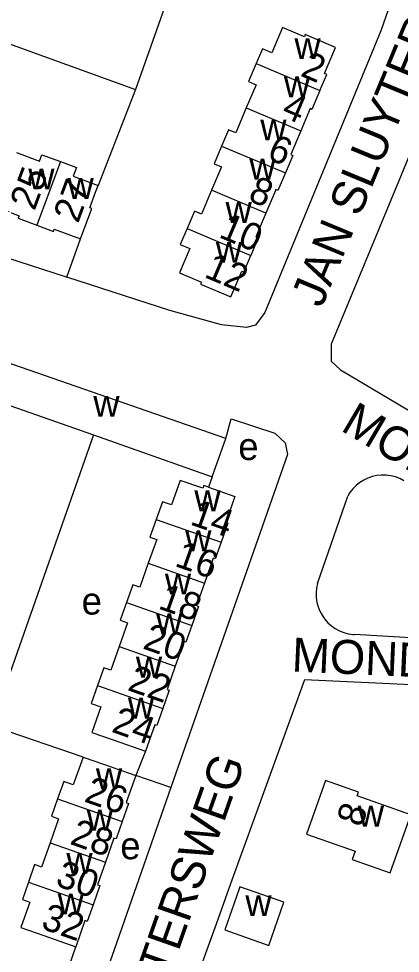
# Model space of a CAD drawing. Extents: x 162804 to 165059, y 381530 to 382901.
# Drawn here: x 163868.3 to 163924.4, y 381888 to 382025.5 of the extents above; entities that cross this region are included whole.
import ezdxf

# ---------------------------------------------------------------- set-up
doc = ezdxf.new("R2010")
doc.units = 0
for name, color, linetype in [('BLT_Basislijn', 7, 'Continuous'), ('BLT_Bebouwing', 7, 'Continuous'), ('BLT_Centroide', 7, 'Continuous'), ('BLT_Huisnummer', 7, 'Continuous'), ('BLT_Huisnummer_ tussenligend', 7, 'Continuous'), ('BLT_Onderverdeling_panden', 7, 'Continuous'), ('BLT_Straatnaam', 7, 'Continuous')]:
    doc.layers.add(name, color=color, linetype=linetype)

msp = doc.modelspace()

# ---------------------------------------------------------------- linework, layer by layer
at = {"layer": 'BLT_Basislijn'}
for p, q in [((163889.95, 382027.81), (163885.4, 382015.06)), ((163858.36, 382024.92), (163885.4, 382015.06)), ((163885.4, 382015.06), (163879.92, 382000.96)), ((163875.33, 381987.49), (163877.35, 381993.11)), ((163879.25, 381964.27), (163866.04, 381926.55)), ((163896.68, 381958.12), (163896.15, 381956.61)), ((163912.16, 381942.4), (163916.64, 381955.29)), ((163952.4, 381932.95), (163917.61, 381934.91)), ((163877.72, 381916.89), (163864.29, 381921.46)), ((163886.88, 381917.75), (163885.45, 381914.17)), ((163890.62, 381912.42), (163885.45, 381914.17)), ((163875.28, 381885.03), (163876.65, 381889))]:
    msp.add_line(p, q, dxfattribs=at)
for points in [[(163895.27, 382041.25), (163919.18, 382032.47), (163921.29, 382031.34), (163922.89, 382029.32), (163922.89, 382027.79), (163921.5, 382023.71), (163904.43, 381982.26), (163903.05, 381980.43), (163901.73, 381980.07), (163898.05, 381980.49), (163890.47, 381982.59), (163875.33, 381987.49)], [(163784.68, 382016.85), (163784.81, 382016.81), (163875.09, 381987.56), (163875.33, 381987.49)], [(163926.54, 382007.48), (163924.12, 382001.64), (163914.2, 381977.63), (163914.2, 381975.14), (163915.57, 381973.87), (163955.79, 381949.95)], [(163898.68, 381963.73), (163899.51, 381966.62), (163905.93, 381964.52), (163907.42, 381963.09), (163907.76, 381961.38), (163891.02, 381913.56), (163890.62, 381912.42)], [(163924.89, 381957.53), (163924.28, 381957.85), (163923.63, 381958.09), (163922.97, 381958.26), (163922.29, 381958.35), (163921.6, 381958.37), (163920.91, 381958.3), (163920.24, 381958.15), (163919.59, 381957.93), (163918.97, 381957.63), (163918.39, 381957.26), (163917.85, 381956.83), (163917.37, 381956.34), (163916.95, 381955.79), (163916.64, 381955.29)], [(163912.16, 381942.4), (163912.03, 381941.72), (163911.97, 381941.03), (163911.99, 381940.34), (163912.09, 381939.65), (163912.27, 381938.99), (163912.53, 381938.35), (163912.86, 381937.74), (163913.25, 381937.17), (163913.71, 381936.65), (163914.23, 381936.19), (163914.79, 381935.79), (163915.4, 381935.46), (163916.04, 381935.21), (163916.71, 381935.03), (163917.39, 381934.92), (163917.61, 381934.91)], [(163948.91, 381926.43), (163910.28, 381928.23), (163899.38, 381898.24), (163897.29, 381892.29), (163887.52, 381865.46)], [(163890.62, 381912.42), (163881.93, 381887.55), (163880.33, 381883.04)]]:
    msp.add_lwpolyline(points, dxfattribs=at)
at = {"layer": 'BLT_Bebouwing'}
for p, q in [((163898.68, 381963.73), (163864.12, 381975.77)), ((163862.17, 381970.28), (163879.25, 381964.27)), ((163879.25, 381964.27), (163896.68, 381958.12)), ((163896.68, 381958.12), (163898.68, 381963.73))]:
    msp.add_line(p, q, dxfattribs=at)
for points in [[(163912.54, 382014.95), (163913.53, 382017.28), (163913.21, 382017.42), (163914.84, 382021.27), (163910.39, 382023.15), (163910.26, 382022.85), (163907.04, 382024.21), (163905.46, 382020.47), (163904.08, 382021.05), (163903.17, 382018.9)], [(163903.17, 382018.9), (163902.05, 382016.24), (163903.14, 382015.78), (163901.7, 382012.38)], [(163912.54, 382014.95), (163911.36, 382012.15), (163911.09, 382012.27), (163909.71, 382009.01)], [(163901.7, 382012.38), (163900.15, 382008.72), (163899.11, 382009.17), (163898.09, 382006.77)], [(163909.71, 382009.01), (163908.24, 382005.52), (163908.55, 382005.39), (163907.46, 382002.82)], [(163898.09, 382006.77), (163896.99, 382004.17), (163898.06, 382003.72), (163896.6, 382000.26)], [(163867.92, 382005.82), (163871.31, 382004.56), (163871.66, 382005.49), (163874.4, 382004.47)], [(163874.4, 382004.47), (163876.73, 382003.6), (163876.26, 382002.32), (163879.92, 382000.96)], [(163907.46, 382002.82), (163906.37, 382000.24), (163906.05, 382000.38), (163905.89, 382000), (163904.58, 381996.9)], [(163877.35, 381993.11), (163879.01, 381997.59), (163878.72, 381997.7), (163879.56, 382000), (163879.92, 382000.96)], [(163896.6, 382000.26), (163895.13, 381996.75), (163894.08, 381997.2), (163893, 381994.64)], [(163864.93, 381997.79), (163868.33, 381996.52), (163868.18, 381996.14), (163870.92, 381995.12)], [(163904.58, 381996.9), (163903.11, 381993.42), (163903.48, 381993.26), (163902.39, 381990.68)], [(163870.92, 381995.12), (163873.37, 381994.22), (163873.49, 381994.55), (163877.35, 381993.11)], [(163893, 381994.64), (163892.01, 381992.3), (163893.41, 381991.71), (163891.89, 381988.12), (163895.11, 381986.76), (163894.98, 381986.45), (163899.43, 381984.57), (163901.04, 381988.37), (163901.36, 381988.23), (163902.39, 381990.68)], [(163896.15, 381956.61), (163895.46, 381956.85), (163895.3, 381956.42), (163891.99, 381957.59), (163890.72, 381953.98), (163889.38, 381954.45), (163888.46, 381951.85)], [(163896.15, 381956.61), (163900.05, 381955.24), (163898.7, 381951.38), (163898.99, 381951.28), (163898.01, 381948.49)], [(163888.46, 381951.85), (163887.55, 381949.24), (163888.54, 381948.89), (163887.3, 381945.39)], [(163898.01, 381948.49), (163897.15, 381946.06), (163896.85, 381946.16), (163895.55, 381942.49)], [(163887.3, 381945.39), (163886.07, 381941.88), (163885.02, 381942.25), (163884.1, 381939.64)], [(163895.55, 381942.49), (163894.39, 381939.17), (163894.69, 381939.06), (163893.71, 381936.26)], [(163884.1, 381939.64), (163883.18, 381937.02), (163884.25, 381936.64), (163883.02, 381933.16)], [(163893.71, 381936.26), (163892.84, 381933.79), (163892.56, 381933.89), (163891.28, 381930.25)], [(163883.02, 381933.16), (163881.79, 381929.67), (163880.76, 381930.03), (163879.83, 381927.4)], [(163891.28, 381930.25), (163890.08, 381926.85), (163890.37, 381926.75), (163889.42, 381924.02)], [(163879.83, 381927.4), (163878.9, 381924.76), (163880.31, 381924.27), (163878.99, 381920.52), (163882.16, 381919.41), (163886.88, 381917.75)], [(163889.42, 381924.02), (163888.54, 381921.54), (163888.25, 381921.64), (163886.88, 381917.75)], [(163877.72, 381916.89), (163876.28, 381912.79), (163874.87, 381913.29), (163873.98, 381910.74)], [(163877.72, 381916.89), (163880.73, 381915.83), (163885.45, 381914.17)], [(163885.45, 381914.17), (163884.05, 381910.2), (163884.41, 381910.07), (163883.47, 381907.4)], [(163925.88, 381908.41), (163918, 381911.18), (163918.2, 381911.75), (163913.34, 381913.47), (163910.55, 381905.56), (163917.7, 381903.04), (163917.27, 381901.83), (163922.86, 381899.86), (163925.88, 381908.41)], [(163873.98, 381910.74), (163873.08, 381908.19), (163874.11, 381907.83), (163872.86, 381904.27)], [(163883.47, 381907.4), (163882.57, 381904.86), (163882.26, 381904.97), (163881, 381901.41)], [(163872.86, 381904.27), (163871.61, 381900.71), (163870.59, 381901.07), (163869.69, 381898.51)], [(163881, 381901.41), (163879.85, 381898.12), (163880.19, 381898), (163879.19, 381895.17)], [(163869.69, 381898.51), (163868.79, 381895.95), (163869.9, 381895.56), (163868.59, 381891.84), (163871.93, 381890.66), (163876.65, 381889)], [(163900.62, 381897.35), (163898.55, 381891.48), (163905.01, 381889.2), (163907.24, 381895.53), (163900.78, 381897.81), (163900.62, 381897.35)], [(163879.19, 381895.17), (163878.33, 381892.72), (163877.99, 381892.84), (163876.65, 381889)]]:
    msp.add_lwpolyline(points, dxfattribs=at)
at = {"layer": 'BLT_Onderverdeling_panden'}
for p, q in [((163903.17, 382018.9), (163912.54, 382014.95)), ((163901.7, 382012.38), (163909.71, 382009.01)), ((163898.09, 382006.77), (163907.46, 382002.82)), ((163874.4, 382004.47), (163870.92, 381995.12)), ((163904.58, 381996.9), (163896.6, 382000.26)), ((163893, 381994.64), (163902.39, 381990.68)), ((163888.46, 381951.85), (163898.01, 381948.49)), ((163887.3, 381945.39), (163895.55, 381942.49)), ((163884.1, 381939.64), (163893.71, 381936.26)), ((163883.02, 381933.16), (163891.28, 381930.25)), ((163879.83, 381927.4), (163889.42, 381924.02)), ((163873.98, 381910.74), (163883.47, 381907.4)), ((163872.86, 381904.27), (163881, 381901.41)), ((163869.69, 381898.51), (163879.19, 381895.17))]:
    msp.add_line(p, q, dxfattribs=at)

# ---------------------------------------------------------------- texts
at = {"layer": 'BLT_Centroide'}
for s, p in [('w', (163908.79, 382019.56)), ('w', (163907.24, 382013.94)), ('w', (163903.77, 382007.59)), ('w', (163902.16, 382001.84)), ('w', (163869.66, 382000.39)), ('w', (163875.42, 381998.97)), ('w', (163898.66, 381995.47)), ('w', (163897.23, 381989.59)), ('w', (163879.22, 381966.94)), ('e', (163900.54, 381960.58)), ('w', (163894.08, 381953.03)), ('w', (163892.73, 381947.16)), ('w', (163889.74, 381940.81)), ('e', (163877.51, 381937.85)), ('w', (163888.45, 381934.94)), ('w', (163885.48, 381928.59)), ('w', (163884.3, 381922.56)), ('w', (163879.6, 381912.16)), ('w', (163878.25, 381906.06)), ('w', (163918.1, 381906.66)), ('e', (163883.19, 381901.86)), ('w', (163875.26, 381899.72)), ('w', (163873.98, 381893.75)), ('w', (163901.57, 381893.5))]:
    msp.add_text(s, height=4, dxfattribs=at).set_placement(p)
at = {"layer": 'BLT_Huisnummer'}
for s, rotation, p in [('2', 337.0781, (163909.52, 382017.14)), ('6', 337.0827, (163904.58, 382004.94)), ('27', 69.6377, (163876.98, 381995.28)), ('12', 337.0956, (163895.37, 381987.54)), ('14', 340.6284, (163893.29, 381951.15)), ('18', 340.6258, (163888.61, 381938.78)), ('24', 340.628, (163881.74, 381920.65)), ('26', 340.6285, (163877.73, 381910.39)), ('8', 70.5631, (163918.65, 381906.44)), ('32', 340.6298, (163871.36, 381891.73))]:
    msp.add_text(s, height=4, rotation=rotation, dxfattribs=at).set_placement(p)
at = {"layer": 'BLT_Huisnummer_ tussenligend'}
for s, rotation, p in [('4', 337.0781, (163906.72, 382011.17)), ('25', 69.6483, (163870.58, 381997.13)), ('8', 337.0827, (163901.8, 381998.82)), ('10', 337.0827, (163897.51, 381993.41)), ('16', 340.6284, (163891.03, 381945.04)), ('20', 340.6258, (163886.34, 381932.9)), ('22', 340.6258, (163884.09, 381926.78)), ('28', 340.6285, (163875.62, 381904.15)), ('30', 340.6285, (163873.49, 381898.04))]:
    msp.add_text(s, height=4, rotation=rotation, dxfattribs=at).set_placement(p)
at = {"layer": 'BLT_Straatnaam'}
for s, rotation, p in [('JAN SLUYTERSWEG', 67.4526, (163912.79, 381982.83)), ('MONDRIAANHOF', 329.4597, (163915.42, 381965.01)), ('MONDRIAANHOF', 357.4597, (163908.33, 381929.48)), ('JAN SLUYTERSWEG', 70.5997, (163879.76, 381854.2))]:
    msp.add_text(s, height=5, rotation=rotation, dxfattribs=at).set_placement(p)

doc.saveas('drawing.dxf')
